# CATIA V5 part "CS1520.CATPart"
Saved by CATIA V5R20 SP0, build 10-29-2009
Part number: CS1520
Revision: 4
Definition: design
Nomenclature: CS1520
Source: made
Description: NOT SPECIFIED
Bounding box of the stored display mesh (mm): x -18.807 to 19, y -19 to 19, z -36 to 9
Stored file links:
  C:\Users\Raffaele\Desktop\3D X SITO CF\BOLEX\20-TILTED COLUMN SUPPORT\CS1520.CATPart
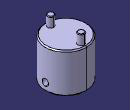
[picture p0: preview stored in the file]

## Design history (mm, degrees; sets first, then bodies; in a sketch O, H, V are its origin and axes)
Body1 "MANIFOLD_SOLID_BREP #695" (main body)
  Solid1: solid without history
